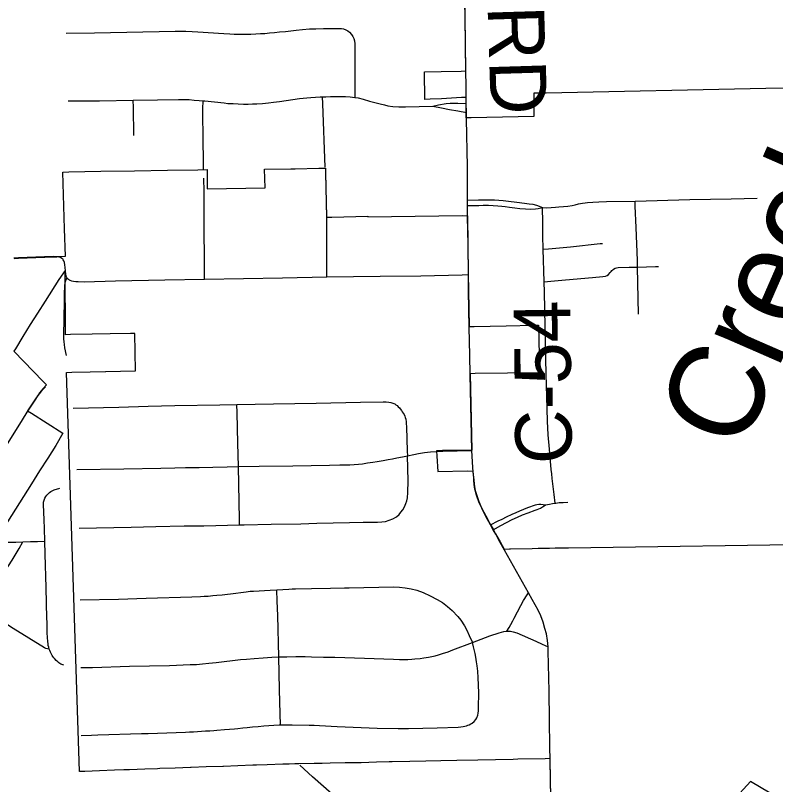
# Model space of a CAD drawing. Extents: x -6.4 to 34, y -4.2 to 22.
# Drawn here: x 3.822 to 4.587, y 16.831 to 17.606 of the extents above; entities that cross this region are included whole.
import ezdxf

# ---------------------------------------------------------------- set-up
doc = ezdxf.new("R2010")
doc.units = 0
for name, color, linetype in [('GM_X_City_Street', 7, 'Continuous'), ('GM_X_Corporation', 7, 'Continuous'), ('GM_X_County_Road', 7, 'Continuous'), ('GM_X_County_Road_Text', 7, 'Continuous'), ('GM_X_Major_River', 7, 'Continuous'), ('GM_X_Major_River_Text', 7, 'Continuous'), ('GM_X_Minor_River', 7, 'Continuous'), ('GM_X_Township_Road', 7, 'Continuous')]:
    doc.layers.add(name, color=color, linetype=linetype)

msp = doc.modelspace()

# ---------------------------------------------------------------- linework, layer by layer
at = {"layer": 'GM_X_City_Street'}
for points in [[(3.87339, 17.58754), (3.90189, 17.58811), (3.98308, 17.58983), (3.98807, 17.58982), (3.9936, 17.5898), (4.00007, 17.58947), (4.00597, 17.58918), (4.03197, 17.58721), (4.038, 17.58694), (4.04255, 17.58673), (4.04894, 17.58667), (4.05439, 17.58661), (4.05921, 17.5868), (4.06435, 17.58701), (4.06901, 17.58724), (4.0732, 17.58746), (4.07795, 17.5879), (4.08299, 17.58836), (4.08809, 17.58889), (4.09402, 17.5895), (4.10495, 17.59081), (4.11129, 17.59138), (4.1182, 17.59195), (4.12462, 17.5921), (4.13227, 17.59228), (4.14609, 17.59251), (4.15028, 17.59234), (4.15261, 17.59197), (4.15479, 17.59118), (4.1568, 17.59005), (4.15862, 17.58856), (4.16061, 17.58639), (4.16191, 17.58446), (4.16286, 17.58235), (4.16344, 17.58008), (4.16379, 17.5771), (4.16398, 17.53031), (4.16401, 17.52293)], [(3.87548, 17.51941), (3.88755, 17.51956), (3.907, 17.51969), (3.9409, 17.52022), (3.96537, 17.52061), (3.98651, 17.52095), (3.99133, 17.52086), (3.9971, 17.52075), (4.00229, 17.52038), (4.00705, 17.52004), (4.01109, 17.51963), (4.01277, 17.51946), (4.03239, 17.51743), (4.03608, 17.51705), (4.04133, 17.51674), (4.04657, 17.51643), (4.05189, 17.51634), (4.05646, 17.51626), (4.06097, 17.51643), (4.06511, 17.51658), (4.07076, 17.51704), (4.07682, 17.51754), (4.08201, 17.5182), (4.08788, 17.51894), (4.10811, 17.52185), (4.11547, 17.52273), (4.11952, 17.52304), (4.12416, 17.52338), (4.12907, 17.52354), (4.13147, 17.52362), (4.1347, 17.52373), (4.13933, 17.52378), (4.14415, 17.52383), (4.14841, 17.52382), (4.15459, 17.52381), (4.15928, 17.52357), (4.16401, 17.52293), (4.16712, 17.52247), (4.17211, 17.52117), (4.17878, 17.51931), (4.18934, 17.51648), (4.19367, 17.51547), (4.19714, 17.51467), (4.20199, 17.51396), (4.2081, 17.51352), (4.21488, 17.51349), (4.24225, 17.5141)], [(3.94132, 17.48456), (3.94099, 17.51298), (3.9409, 17.52022)], [(4.13397, 17.45275), (4.13178, 17.51655), (4.13147, 17.52362)], [(4.24225, 17.5141), (4.24795, 17.51551), (4.25563, 17.51682), (4.25979, 17.51718), (4.26382, 17.51732), (4.26751, 17.51731), (4.27608, 17.51701)], [(4.24225, 17.5141), (4.2512, 17.51242), (4.25911, 17.51099), (4.26762, 17.50944), (4.27617, 17.50794)], [(4.27728, 17.41972), (4.28841, 17.41992), (4.29241, 17.42), (4.29646, 17.42007), (4.30038, 17.41997), (4.30453, 17.41986), (4.30881, 17.4195), (4.31318, 17.41914), (4.3186, 17.4185), (4.32687, 17.41753), (4.33462, 17.41661), (4.33935, 17.41606), (4.34303, 17.41549), (4.34655, 17.41457), (4.34939, 17.41357), (4.35275, 17.41212)], [(4.35275, 17.41212), (4.35712, 17.41204), (4.36157, 17.41226), (4.36592, 17.41256), (4.36922, 17.41279), (4.37374, 17.41317), (4.37818, 17.41371), (4.38246, 17.41434), (4.38577, 17.41504), (4.38912, 17.41574), (4.39289, 17.41653), (4.39558, 17.41685), (4.39795, 17.41714), (4.40338, 17.41752), (4.40951, 17.41789), (4.41717, 17.41812), (4.4459, 17.41863), (4.50103, 17.42013), (4.54269, 17.42095), (4.56866, 17.42146)], [(4.27731, 17.4143), (4.28858, 17.41439), (4.29302, 17.41443), (4.29852, 17.41447), (4.30314, 17.41425), (4.30781, 17.41403), (4.31171, 17.41362), (4.31522, 17.41325), (4.3196, 17.41268), (4.32503, 17.41195), (4.32998, 17.4113), (4.33568, 17.41082), (4.34104, 17.41067), (4.34579, 17.41082), (4.34847, 17.4112), (4.35275, 17.41212)], [(4.36544, 17.11462), (4.36442, 17.12329), (4.36253, 17.13933), (4.36198, 17.14402), (4.36156, 17.14851), (4.35965, 17.16894), (4.35853, 17.18354), (4.35783, 17.19702), (4.35714, 17.22194), (4.35643, 17.2444), (4.35554, 17.2923), (4.35465, 17.32701), (4.35438, 17.3375), (4.35351, 17.37018), (4.35316, 17.38358), (4.35297, 17.39727), (4.35275, 17.41212)], [(4.44933, 17.3049), (4.44836, 17.35225), (4.44822, 17.35882), (4.44702, 17.39198), (4.44612, 17.41351), (4.4459, 17.41863)], [(4.35351, 17.37018), (4.35893, 17.37068), (4.38098, 17.37271), (4.41078, 17.37582), (4.41326, 17.37609)], [(4.35438, 17.3375), (4.36107, 17.3381), (4.37587, 17.33943), (4.40306, 17.34182), (4.41358, 17.3427), (4.41603, 17.34313), (4.41787, 17.34392), (4.41919, 17.34494), (4.4209, 17.34685), (4.42173, 17.34779), (4.42249, 17.34865), (4.4235, 17.34956), (4.42434, 17.3503), (4.42578, 17.35118), (4.42708, 17.35164), (4.42892, 17.35185), (4.44002, 17.35201), (4.44836, 17.35225), (4.46648, 17.35278), (4.46953, 17.35281)], [(3.87371, 17.26338), (3.87211, 17.27094), (3.87157, 17.27419), (3.87129, 17.27695), (3.87104, 17.28007), (3.87101, 17.28319), (3.87163, 17.3182), (3.87169, 17.32665), (3.87182, 17.33164), (3.87201, 17.33374), (3.87231, 17.33593), (3.87272, 17.33786), (3.87405, 17.34158)], [(3.87088, 16.95158), (3.86804, 16.95272), (3.86607, 16.95403), (3.86493, 16.95502), (3.86335, 16.95639), (3.86198, 16.95788), (3.86091, 16.95906), (3.85998, 16.96037), (3.8592, 16.96148), (3.85831, 16.96318), (3.85751, 16.96468), (3.85683, 16.96641), (3.85634, 16.96765), (3.85578, 16.96959), (3.85528, 16.97153), (3.85503, 16.97329), (3.85477, 16.97513), (3.85451, 16.97974), (3.85429, 16.98374), (3.85424, 16.98734), (3.85419, 16.99054), (3.85408, 16.99485), (3.85398, 16.99861), (3.85317, 17.02966), (3.85232, 17.06317), (3.85191, 17.0764), (3.8515, 17.0892), (3.85118, 17.09793), (3.85058, 17.11342), (3.85064, 17.11574), (3.85111, 17.11774), (3.85183, 17.11957), (3.85268, 17.12129), (3.85384, 17.12269), (3.85493, 17.12386), (3.85666, 17.12546), (3.85772, 17.12624), (3.85909, 17.12711), (3.8612, 17.12806), (3.86702, 17.12971)], [(4.30025, 17.09292), (4.30811, 17.09671), (4.31215, 17.09867), (4.31653, 17.10079), (4.32208, 17.10347), (4.32611, 17.10531), (4.32998, 17.10707), (4.33803, 17.11032), (4.3456, 17.11292), (4.3469, 17.11334), (4.34894, 17.11371), (4.35103, 17.1136), (4.35328, 17.11339), (4.35574, 17.11286)], [(4.30313, 17.08795), (4.31097, 17.09219), (4.31657, 17.09522), (4.32206, 17.09804), (4.32745, 17.1006), (4.33252, 17.10285), (4.33821, 17.10504), (4.3452, 17.10745), (4.34736, 17.10828), (4.3492, 17.10901), (4.35072, 17.10973), (4.35286, 17.11093), (4.35433, 17.11188), (4.35574, 17.11286)], [(4.35574, 17.11286), (4.35966, 17.11368), (4.3629, 17.11427), (4.36544, 17.11462), (4.36609, 17.1147), (4.36944, 17.11516), (4.37341, 17.11547), (4.37817, 17.11567)], [(3.85634, 16.96765), (3.8544, 16.96808), (3.85286, 16.96851), (3.85165, 16.96903), (3.82013, 16.98846), (3.81014, 16.99477), (3.80015, 17.00114), (3.7976, 17.00309), (3.79667, 17.00407), (3.79578, 17.00499), (3.79501, 17.00612), (3.79429, 17.00718), (3.79347, 17.00908), (3.79312, 17.01114), (3.79323, 17.01317), (3.79347, 17.01427), (3.7938, 17.01573), (3.79423, 17.01724), (3.79494, 17.01876), (3.79731, 17.02324), (3.8093, 17.04216), (3.81908, 17.05726), (3.82594, 17.06903), (3.82966, 17.07572)], [(3.80353, 17.07732), (3.80522, 17.07657), (3.80745, 17.07586), (3.80889, 17.07559), (3.81039, 17.07539), (3.81237, 17.07526), (3.81462, 17.07523), (3.82253, 17.07544), (3.82966, 17.07572), (3.83726, 17.07602), (3.84447, 17.0762), (3.85191, 17.0764)]]:
    msp.add_lwpolyline(points, dxfattribs=at)
at = {"layer": 'GM_X_Corporation'}
for points in [[(4.60971, 17.53248), (4.57762, 17.53182), (4.35636, 17.52728), (4.34404, 17.52712), (4.34402, 17.50368), (4.28091, 17.50241), (4.27602, 17.50233), (4.27597, 17.50849), (4.27588, 17.51756), (4.27578, 17.52285), (4.27117, 17.52281), (4.25101, 17.52175), (4.23958, 17.52115), (4.23424, 17.52102), (4.23388, 17.54889), (4.25071, 17.5491), (4.27083, 17.54936), (4.27548, 17.54961), (4.27477, 17.60429), (4.2742, 17.63243)], [(3.82074, 17.36158), (3.82524, 17.36175), (3.86037, 17.36311), (3.86369, 17.36304), (3.87257, 17.36331), (3.87161, 17.39074), (3.86997, 17.44787), (3.87607, 17.4481), (3.90809, 17.44862), (3.94219, 17.44918), (3.97543, 17.44973), (4.00567, 17.45022), (4.01515, 17.45031), (4.01535, 17.43111), (4.07344, 17.4321), (4.07302, 17.45086), (4.09955, 17.45111), (4.10383, 17.4512), (4.1276, 17.45166), (4.12854, 17.45168), (4.12949, 17.4517), (4.13438, 17.45182), (4.13435, 17.44755), (4.13541, 17.40251), (4.13973, 17.40263), (4.14068, 17.40265), (4.177, 17.40337), (4.17706, 17.40268), (4.27212, 17.40409), (4.27716, 17.40378), (4.27774, 17.37505), (4.27801, 17.34527), (4.27816, 17.32883), (4.27885, 17.29243), (4.28384, 17.29243), (4.31606, 17.29313), (4.34412, 17.29374), (4.34876, 17.29384), (4.34948, 17.26376), (4.34991, 17.24591), (4.31745, 17.24549), (4.28503, 17.24507), (4.27991, 17.24495), (4.28156, 17.16806), (4.25222, 17.16763), (4.24876, 17.16745), (4.2461, 17.1673), (4.24629, 17.16198), (4.2473, 17.14641), (4.27731, 17.14703), (4.28276, 17.14682), (4.28306, 17.14362), (4.28329, 17.14068), (4.28348, 17.1378), (4.2839, 17.13422), (4.28427, 17.13116), (4.28458, 17.12931), (4.28506, 17.12736), (4.28589, 17.12441), (4.28691, 17.12119), (4.28859, 17.11646), (4.29134, 17.11006), (4.29556, 17.10189), (4.30005, 17.09347), (4.30293, 17.08851), (4.30549, 17.0839), (4.31004, 17.07563), (4.31417, 17.06844), (4.31956, 17.06865), (4.32063, 17.06867), (4.34247, 17.0691), (4.34822, 17.06922), (4.35205, 17.06929), (4.35589, 17.06937), (4.3599, 17.06945), (4.36559, 17.06956), (4.36937, 17.06964), (4.37316, 17.06971), (4.37885, 17.06982), (4.64907, 17.07378)], [(4.36139, 16.803), (4.36076, 16.83595), (4.36031, 16.85764), (4.35542, 16.85749), (4.32804, 16.85691), (4.3233, 16.85681), (4.28782, 16.85606), (4.26649, 16.85561), (4.25039, 16.85527), (4.23524, 16.85495), (4.21913, 16.85469), (4.20157, 16.8544), (4.19846, 16.85418), (4.18559, 16.85387), (4.17038, 16.85343), (4.16419, 16.85346), (4.15424, 16.8533), (4.13903, 16.85293), (4.13104, 16.85276), (4.12303, 16.85259), (4.10735, 16.85226), (4.10353, 16.85218), (4.09788, 16.85206), (4.09127, 16.85192), (4.07567, 16.85136), (4.06474, 16.85096), (4.06119, 16.85083), (4.04604, 16.85028), (4.03159, 16.84976), (4.03089, 16.84974), (4.01413, 16.84913), (3.99914, 16.84859), (3.99846, 16.84856), (3.98287, 16.848), (3.96765, 16.84745), (3.96531, 16.84737), (3.95243, 16.8469), (3.93721, 16.84635), (3.93131, 16.84613), (3.92199, 16.8458), (3.90677, 16.84525), (3.89209, 16.84472), (3.88658, 16.84467), (3.87365, 17.24622), (3.87912, 17.24664), (3.89763, 17.24695), (3.91279, 17.24721), (3.91336, 17.24722), (3.92795, 17.24747), (3.94311, 17.24773), (3.94246, 17.28552), (3.94151, 17.28551), (3.93816, 17.28544), (3.91766, 17.28505), (3.89937, 17.2847), (3.87778, 17.28429), (3.8726, 17.28423), (3.87217, 17.34884), (3.8659, 17.33978), (3.85212, 17.31802), (3.84455, 17.306), (3.83716, 17.2943), (3.83353, 17.28856), (3.82957, 17.28229), (3.82224, 17.27011), (3.8208, 17.2677), (3.85023, 17.23715), (3.85343, 17.23385), (3.84987, 17.22982), (3.84813, 17.22784), (3.84656, 17.22571), (3.84474, 17.22315), (3.84247, 17.21972), (3.83451, 17.20768), (3.83849, 17.20516), (3.86981, 17.18497), (3.86286, 17.17266), (3.85474, 17.15986), (3.84662, 17.14706), (3.83849, 17.13426), (3.83037, 17.12146), (3.82225, 17.10867), (3.81412, 17.09587)]]:
    msp.add_lwpolyline(points, dxfattribs=at)
at = {"layer": 'GM_X_County_Road'}
for p, q in [((4.27622, 17.50114), (4.27617, 17.50794)), ((4.27719, 17.43621), (4.27711, 17.45238)), ((4.28176, 17.1675), (4.28011, 17.24368))]:
    msp.add_line(p, q, dxfattribs=at)
for points in [[(4.27569, 17.54832), (4.27497, 17.60374), (4.27449, 17.62971)], [(4.27597, 17.52293), (4.27598, 17.53533), (4.27569, 17.54832)], [(4.27617, 17.50794), (4.27608, 17.51701), (4.27597, 17.52293)], [(4.27711, 17.45238), (4.2771, 17.45333), (4.27622, 17.50114)], [(4.27736, 17.40323), (4.27731, 17.4143), (4.27728, 17.41972), (4.27719, 17.43621)], [(4.27906, 17.29132), (4.27836, 17.32827), (4.27821, 17.34472), (4.27794, 17.37449), (4.27736, 17.40323)], [(4.28011, 17.24368), (4.27963, 17.26366), (4.27906, 17.29132)], [(4.28296, 17.14626), (4.28262, 17.15063), (4.28231, 17.15628), (4.28176, 17.1675)], [(4.31461, 17.06747), (4.31024, 17.07508), (4.30569, 17.08335), (4.30313, 17.08795), (4.30025, 17.09292), (4.29576, 17.10134), (4.29154, 17.10951), (4.28878, 17.11591), (4.28711, 17.12064), (4.28609, 17.12386), (4.28526, 17.12681), (4.28478, 17.12876), (4.28447, 17.1306), (4.2841, 17.13366), (4.28368, 17.13725), (4.28348, 17.14012), (4.28326, 17.14307), (4.28296, 17.14626)], [(4.36046, 16.8564), (4.36026, 16.86949), (4.35996, 16.89619), (4.35933, 16.9253), (4.35847, 16.96575), (4.35832, 16.96996), (4.35769, 16.97639), (4.35671, 16.98299), (4.35523, 16.9885), (4.35347, 16.9949), (4.35101, 17.00139), (4.34836, 17.00701), (4.34246, 17.01768), (4.33872, 17.02451), (4.31461, 17.06747)], [(4.3616, 16.80187), (4.36096, 16.8354), (4.36046, 16.8564)]]:
    msp.add_lwpolyline(points, dxfattribs=at)
at = {"layer": 'GM_X_Major_River'}
msp.add_lwpolyline([(4.58195, 16.82271), (4.56201, 16.83443), (4.54423, 16.81507)], dxfattribs=at)
at = {"layer": 'GM_X_Minor_River'}
msp.add_lwpolyline([(4.14061, 16.82202), (4.12132, 16.83907), (4.10857, 16.85094)], dxfattribs=at)
at = {"layer": 'GM_X_Township_Road'}
for p, q in [((4.13561, 17.40212), (4.13455, 17.447)), ((4.01207, 17.42845), (4.01194, 17.4416))]:
    msp.add_line(p, q, dxfattribs=at)
for points in [[(4.01159, 17.45042), (4.01157, 17.46446), (4.01137, 17.47504), (4.0111, 17.48987), (4.01093, 17.49924), (4.01103, 17.51163), (4.01109, 17.51963)], [(4.01252, 17.34015), (4.01208, 17.41031), (4.01207, 17.42845)], [(4.13572, 17.34255), (4.13563, 17.40112), (4.13561, 17.40212)], [(3.82094, 17.36103), (3.82544, 17.36119), (3.86057, 17.36256), (3.86389, 17.36248)], [(3.87405, 17.34158), (3.87359, 17.3425), (3.87323, 17.34363), (3.87298, 17.34496), (3.87273, 17.34835), (3.87242, 17.35175), (3.87212, 17.35466), (3.87171, 17.35671), (3.87094, 17.35865), (3.87043, 17.35957), (3.86982, 17.36029), (3.86906, 17.36105), (3.86771, 17.36175), (3.86598, 17.36221), (3.86389, 17.36248)], [(3.87405, 17.34158), (3.87477, 17.34071), (3.87553, 17.34005), (3.87629, 17.33949), (3.87716, 17.33902), (3.87864, 17.33851), (3.88064, 17.33815), (3.88299, 17.3379), (3.88552, 17.33773), (3.8913, 17.33757), (3.92308, 17.3383), (3.97265, 17.33948), (4.01252, 17.34015), (4.09103, 17.34152), (4.13572, 17.34255), (4.1892, 17.34316), (4.23024, 17.3436), (4.27191, 17.34457), (4.27821, 17.34472)], [(3.8342, 17.20634), (3.83471, 17.20713), (3.84267, 17.21917), (3.84494, 17.2226), (3.84676, 17.22516), (3.84833, 17.22728), (3.85007, 17.22927), (3.85244, 17.2318)], [(3.88021, 17.21018), (3.92624, 17.21136), (3.956, 17.21212), (3.98267, 17.21282), (4.02797, 17.21349), (4.04497, 17.21384), (4.08194, 17.2146), (4.1248, 17.21519), (4.1694, 17.21643), (4.19248, 17.21658), (4.1953, 17.21648), (4.19793, 17.21626), (4.20016, 17.21581), (4.20213, 17.21527), (4.20396, 17.21447), (4.20517, 17.21376), (4.20633, 17.21286), (4.20753, 17.2117), (4.20865, 17.21049), (4.20958, 17.20951), (4.21083, 17.20795), (4.21164, 17.20673), (4.21249, 17.20535), (4.21338, 17.20375), (4.21414, 17.20227), (4.21458, 17.20093), (4.21503, 17.19923), (4.21538, 17.19655), (4.21556, 17.19485), (4.21574, 17.1916), (4.21667, 17.16699), (4.21685, 17.16238)], [(4.04783, 17.09281), (4.04774, 17.09812), (4.04681, 17.15156), (4.046, 17.17517), (4.04528, 17.20568), (4.04497, 17.21384)], [(3.71547, 16.98993), (3.72592, 17.00606), (3.72997, 17.01304), (3.73318, 17.01982), (3.73602, 17.02586), (3.73812, 17.03104), (3.74004, 17.03715), (3.74134, 17.04251), (3.74331, 17.0504), (3.7453, 17.05805), (3.74702, 17.06409), (3.74937, 17.07026), (3.75166, 17.07479), (3.7531, 17.07765), (3.75614, 17.083), (3.75964, 17.08845), (3.76418, 17.0955), (3.76723, 17.10029), (3.77185, 17.10756), (3.80106, 17.15377), (3.82919, 17.19846), (3.8342, 17.20634)], [(3.88397, 17.1484), (3.93127, 17.14914), (3.96856, 17.14998), (3.98285, 17.1502), (3.99343, 17.1504), (4.00711, 17.15069), (4.02079, 17.15104), (4.03533, 17.15133), (4.04681, 17.15156), (4.06741, 17.15197), (4.10162, 17.1523), (4.13827, 17.15298), (4.14881, 17.15323), (4.15894, 17.15338), (4.16309, 17.15354), (4.16757, 17.15384), (4.17157, 17.15439), (4.17652, 17.15509), (4.18185, 17.15589), (4.18649, 17.15662), (4.19238, 17.15762), (4.19728, 17.15844), (4.20186, 17.15921), (4.20611, 17.16011), (4.21187, 17.16133), (4.21685, 17.16238), (4.22316, 17.16369), (4.22787, 17.16467), (4.23413, 17.16565), (4.24017, 17.16635), (4.2463, 17.16674)], [(4.2463, 17.16674), (4.24896, 17.1669), (4.25242, 17.16708), (4.28176, 17.1675)], [(3.88648, 17.08948), (3.93868, 17.09048), (3.96355, 17.09105), (3.99212, 17.09167), (4.01201, 17.09181), (4.04783, 17.09281), (4.05243, 17.09294), (4.07971, 17.0935), (4.10955, 17.09399), (4.12571, 17.09443), (4.15861, 17.09517), (4.17228, 17.09542), (4.18659, 17.09544), (4.19101, 17.09571), (4.19476, 17.09634), (4.19851, 17.09747), (4.202, 17.09895), (4.20567, 17.10104), (4.20846, 17.10331), (4.21029, 17.10566), (4.21213, 17.1081), (4.21379, 17.11098), (4.21518, 17.11421), (4.21615, 17.117), (4.21685, 17.12013), (4.21731, 17.12522), (4.21741, 17.13707), (4.21685, 17.16238)], [(3.88746, 17.01727), (3.92589, 17.01811), (3.95386, 17.01889), (3.99966, 17.02022), (4.00836, 17.0207), (4.01236, 17.02091), (4.01634, 17.02113), (4.02079, 17.02155), (4.02498, 17.02194), (4.03023, 17.0225), (4.03554, 17.02316), (4.03863, 17.02354), (4.05451, 17.02551), (4.05635, 17.02574), (4.05839, 17.02598), (4.06034, 17.0261), (4.06197, 17.0262), (4.07852, 17.0272), (4.0855, 17.02757), (4.09758, 17.02819), (4.10089, 17.02836), (4.10411, 17.02844), (4.12013, 17.02882), (4.13924, 17.02921), (4.15336, 17.02936), (4.15539, 17.02939), (4.15821, 17.02943), (4.20261, 17.03052), (4.20891, 17.0301), (4.21452, 17.02954), (4.22071, 17.02846), (4.22619, 17.02697), (4.23269, 17.02462), (4.23954, 17.02151), (4.24673, 17.01779), (4.25206, 17.01453), (4.25709, 17.01077), (4.26172, 17.00657), (4.26737, 17.0007), (4.27052, 16.9968), (4.27423, 16.99106), (4.27669, 16.98685), (4.27907, 16.98137), (4.28216, 16.97427)], [(4.08909, 16.89155), (4.08875, 16.90248), (4.08798, 16.92718), (4.08735, 16.95986), (4.08626, 17.0016), (4.08585, 17.0159), (4.0855, 17.02757)], [(4.31684, 16.98571), (4.31908, 16.98958), (4.32072, 16.99244), (4.32292, 16.99625), (4.32427, 16.99888), (4.33091, 17.0118), (4.33362, 17.01666), (4.33486, 17.01857), (4.33596, 17.02026), (4.33872, 17.02451)], [(3.88817, 16.94938), (3.89971, 16.9494), (3.9369, 16.95046), (3.97719, 16.95135), (3.99827, 16.95217), (4.0045, 16.95241), (4.01068, 16.95285), (4.01694, 16.95351), (4.02417, 16.95428), (4.04883, 16.95721), (4.05493, 16.95777), (4.06242, 16.95845), (4.07149, 16.95904), (4.08036, 16.95962), (4.08735, 16.95986), (4.09525, 16.96013), (4.10446, 16.96018), (4.10868, 16.96021), (4.11385, 16.96023), (4.12028, 16.96004), (4.13247, 16.95967), (4.14366, 16.9595), (4.17346, 16.95871), (4.20263, 16.95756), (4.20896, 16.95741), (4.21447, 16.95728), (4.2172, 16.95738), (4.22135, 16.95753), (4.22441, 16.95783), (4.22945, 16.95834), (4.23329, 16.95892), (4.23811, 16.95965), (4.24148, 16.96039), (4.24484, 16.96112), (4.248, 16.96202), (4.25206, 16.96318), (4.25765, 16.96515), (4.26265, 16.9669), (4.28216, 16.97427), (4.29984, 16.98097), (4.3092, 16.98412), (4.31144, 16.98473), (4.31391, 16.98534), (4.31684, 16.98571), (4.31837, 16.98582), (4.32042, 16.98573), (4.32335, 16.98523), (4.32681, 16.98414), (4.34617, 16.97586), (4.35226, 16.9729), (4.35832, 16.96996)], [(3.88834, 16.88086), (3.89883, 16.88119), (3.90504, 16.88135), (3.94906, 16.88273), (3.95157, 16.88281), (3.95593, 16.88296), (3.99352, 16.8843), (3.99734, 16.88444), (4.00138, 16.88466), (4.01368, 16.88535), (4.01784, 16.88558), (4.02183, 16.88591), (4.02506, 16.88618), (4.03266, 16.8868), (4.03769, 16.88722), (4.04262, 16.88762), (4.04607, 16.88798), (4.05099, 16.88848), (4.0556, 16.88895), (4.06097, 16.88945), (4.06645, 16.88995), (4.07232, 16.8905), (4.07721, 16.89095), (4.08245, 16.89125), (4.08771, 16.89154), (4.08909, 16.89155), (4.0918, 16.89157), (4.09595, 16.8916), (4.10071, 16.89164), (4.11799, 16.89124), (4.12305, 16.89113), (4.12832, 16.89087), (4.14599, 16.89003), (4.18634, 16.88824), (4.20737, 16.88784), (4.21787, 16.88788), (4.24687, 16.88866), (4.26791, 16.88926), (4.27057, 16.88951), (4.27295, 16.88974), (4.27609, 16.89047), (4.27756, 16.89106), (4.27908, 16.89168), (4.28045, 16.89249), (4.28187, 16.89334), (4.28391, 16.895), (4.28566, 16.89698), (4.28672, 16.89868), (4.28773, 16.90113), (4.28815, 16.90339), (4.28837, 16.90556), (4.28841, 16.90943), (4.28859, 16.92348), (4.28831, 16.93191), (4.28811, 16.93886), (4.28769, 16.94547), (4.2869, 16.95087), (4.28629, 16.95509), (4.28549, 16.95967), (4.28482, 16.96345), (4.28335, 16.97005), (4.28216, 16.97427)]]:
    msp.add_lwpolyline(points, dxfattribs=at)

# ---------------------------------------------------------------- texts
at = {"layer": 'GM_X_County_Road_Text'}
for s, rotation, p in [('NORTH RD', 271.7471, (4.28859, 17.90567)), ('C-54', 90.6874, (4.38246, 17.15433))]:
    msp.add_text(s, height=0.056818, rotation=rotation, dxfattribs=at).set_placement(p)
at = {"layer": 'GM_X_Major_River_Text'}
msp.add_text('Creek', height=0.094754, rotation=66.39251, dxfattribs=at).set_placement((4.55256, 17.16413))

doc.saveas('drawing.dxf')
